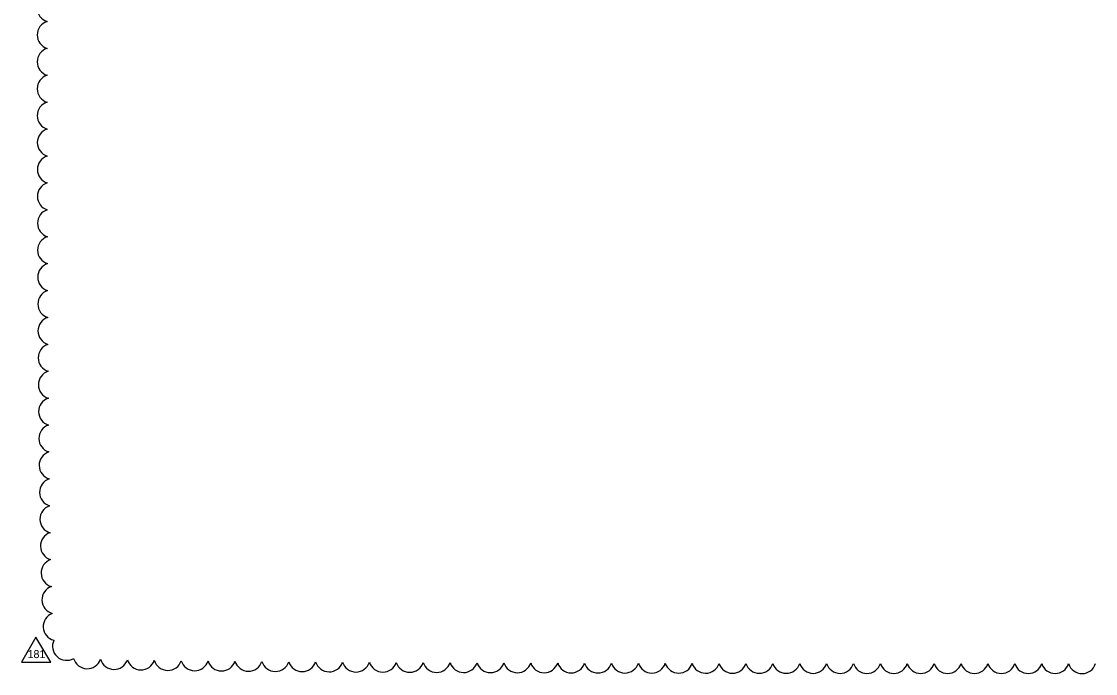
# Model space of a CAD drawing. Extents: x -811.2 to -767.6, y -2295.2 to -2235.1.
# Drawn here: x -811.23 to -803.18, y -2257.21 to -2252.32 of the extents above; entities that cross this region are included whole.
import ezdxf

# ---------------------------------------------------------------- set-up
doc = ezdxf.new("R2010")
doc.units = 0
doc.layers.add('Cloud_dp', color=7, linetype='Continuous')

msp = doc.modelspace()

# ---------------------------------------------------------------- linework, layer by layer
at = {"layer": 'Cloud_dp'}
msp.add_lwpolyline([(-811.1249, -2256.9342), (-811.2327, -2257.1223), (-811.012, -2257.1223)], close=True, dxfattribs=at)
for centre, start, end in [((-811.0091, -2252.2228), 107.49843, 252.49843), ((-811.0091, -2252.4243), 107.51148, 252.51148), ((-811.009, -2252.6259), 107.53101, 252.53101), ((-811.0089, -2252.8274), 107.55191, 252.55191), ((-811.0087, -2253.0289), 107.57435, 252.57435), ((-811.0084, -2253.2305), 107.59852, 252.59852), ((-811.008, -2253.432), 107.62468, 252.62468), ((-811.0075, -2253.6335), 107.65309, 252.65309), ((-811.0069, -2253.8351), 107.68411, 252.68411), ((-811.0062, -2254.0366), 107.71817, 252.71817), ((-811.0053, -2254.2381), 107.75578, 252.75578), ((-811.0044, -2254.4396), 107.79762, 252.79762), ((-811.0032, -2254.6412), 107.84454, 252.84454), ((-811.0019, -2254.8427), 107.89767, 252.89767), ((-811.0004, -2255.0442), 107.95851, 252.95851), ((-810.9987, -2255.2457), 108.02912, 253.02912), ((-810.9967, -2255.4472), 108.11243, 253.11243), ((-810.9944, -2255.6487), 108.21279, 253.21279), ((-810.9916, -2255.8501), 108.33694, 253.33694), ((-810.9884, -2256.0516), 108.49611, 253.49611), ((-810.9845, -2256.253), 108.71068, 253.71068), ((-810.9797, -2256.4543), 109.02298, 254.02298), ((-810.9735, -2256.6554), 109.54201, 254.54201), ((-810.9643, -2256.8561), 110.71007, 255.71007), ((-810.8945, -2257.0031), 155.06518, 300.06518), ((-810.7398, -2257.066), 195.62937, 340.62937), ((-810.5387, -2257.0715), 196.26473, 341.26473), ((-810.3374, -2257.0753), 196.54985, 341.54985), ((-810.1359, -2257.0784), 196.72204, 341.72204), ((-809.9345, -2257.0809), 196.84059, 341.84059), ((-809.733, -2257.083), 196.92865, 341.92865), ((-809.5315, -2257.0849), 196.99739, 341.99739), ((-809.33, -2257.0866), 197.053, 342.053), ((-809.1284, -2257.0881), 197.09919, 342.09919), ((-808.9269, -2257.0894), 197.13834, 342.13834), ((-808.7254, -2257.0907), 197.17209, 342.17209), ((-808.5239, -2257.0918), 197.20158, 342.20158), ((-808.3223, -2257.0928), 197.22762, 342.22762), ((-808.1208, -2257.0937), 197.25085, 342.25085), ((-807.9193, -2257.0945), 197.27174, 342.27174), ((-807.7177, -2257.0953), 197.29065, 342.29065), ((-807.5162, -2257.096), 197.30788, 342.30788), ((-807.3147, -2257.0966), 197.32367, 342.32367), ((-807.1131, -2257.0972), 197.3382, 342.3382), ((-806.9116, -2257.0978), 197.35163, 342.35163), ((-806.71, -2257.0983), 197.3641, 342.3641), ((-806.5085, -2257.0987), 197.37571, 342.37571), ((-806.3069, -2257.0992), 197.38657, 342.38657), ((-806.1054, -2257.0995), 197.39674, 342.39674), ((-805.9039, -2257.0999), 197.40629, 342.40629), ((-805.7023, -2257.1002), 197.4153, 342.4153), ((-805.5008, -2257.1005), 197.4238, 342.4238), ((-805.2992, -2257.1007), 197.43184, 342.43184), ((-805.0977, -2257.101), 197.43947, 342.43947), ((-804.8961, -2257.1012), 197.44671, 342.44671), ((-804.6946, -2257.1013), 197.4536, 342.4536), ((-804.493, -2257.1015), 197.46017, 342.46017), ((-804.2915, -2257.1016), 197.46644, 342.46644), ((-804.09, -2257.1017), 197.47243, 342.47243), ((-803.8884, -2257.1018), 197.47816, 342.47816), ((-803.6869, -2257.1019), 197.48365, 342.48365), ((-803.4853, -2257.1019), 197.48892, 342.48892), ((-803.2838, -2257.102), 197.49398, 342.49398)]:
    msp.add_arc(centre, 0.1057, start, end, dxfattribs=at)

# ---------------------------------------------------------------- texts
msp.add_text('181', height=0.05998, rotation=0, dxfattribs=at).set_placement((-811.1872, -2257.0922))

doc.saveas('drawing.dxf')
